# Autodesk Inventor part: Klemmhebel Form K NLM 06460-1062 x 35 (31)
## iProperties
Title: Klemmhebel Form K NLM 06460-1062 x 35 (31)
Author: AGeddert
Company: Cadenas Solutions GmbH
Length Units: 11269
Angle Units: 11283
Time Units: 11279
Mass Units: 11290
Length Display Precision: 3
Angle Display Precision: 1
Compacted: False
PropertySet Name: _Private Model Information
Created: 2002-10
Part Number: Klemmhebel M6x35
Document SubType Name: Modellieren
Designer: AGeddert
Control State: 0
Master: False
Checked Out: False
PropertySet Name: Design Tracking Control
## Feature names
1. Drehung1 [Revolution]
2. Extrusion1
3. Extrusion2
4. Extrusion3
5. Extrusion4
